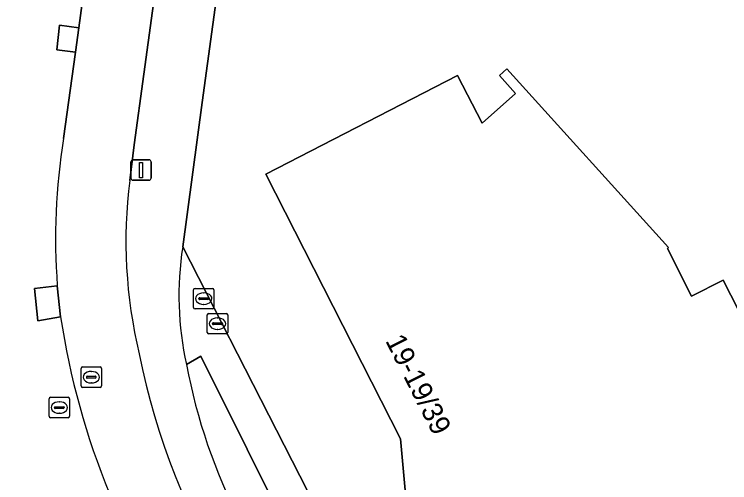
# Model space of a CAD drawing. Extents: x 161402 to 161933, y 381647 to 382315.
# Drawn here: x 161753.62 to 161788.66, y 381978.86 to 382001.78 of the extents above; entities that cross this region are included whole.
import ezdxf

# ---------------------------------------------------------------- set-up
doc = ezdxf.new("R2010")
doc.units = 0
for name, color, linetype in [('IMGEO_Erf', 7, 'Continuous'), ('IMGEO_Groenvoorziening', 7, 'Continuous'), ('IMGEO_Lichtmast', 7, 'Continuous'), ('IMGEO_Pand', 7, 'Continuous'), ('IMGEO_Pand_nummerreeks', 7, 'Continuous'), ('IMGEO_Rijbaan_lokaal_open', 7, 'Continuous'), ('IMGEO_Rioolput', 7, 'Continuous'), ('IMGEO_Voetpad_open', 7, 'Continuous')]:
    doc.layers.add(name, color=color, linetype=linetype)

msp = doc.modelspace()

# ---------------------------------------------------------------- linework, layer by layer
at = {"layer": 'IMGEO_Erf'}
for points in [[(161773.703, 382076.916), (161762.821, 381997.456), (161761.87, 381990.395), (161771.057, 381972.467), (161771.173, 381972.261), (161771.575, 381971.547), (161771.72, 381971.27), (161774.483, 381972.736)], [(161772.785, 381978.319), (161772.541, 381981.009), (161765.944, 381993.952), (161775.334, 381998.777), (161776.531, 381996.448), (161778.17, 381997.911), (161777.382, 381998.782), (161777.752, 381999.117), (161785.669, 381990.368), (161785.621, 381990.324), (161786.795, 381987.989), (161788.334, 381988.775), (161795.171, 381975.426), (161794.738, 381975.207), (161794.625, 381975.432), (161790.711, 381973.405), (161791.79, 381971.32), (161780.758, 381965.653), (161781.596, 381964.647), (161815.795, 381959.903)]]:
    msp.add_lwpolyline(points, dxfattribs=at)
at = {"layer": 'IMGEO_Groenvoorziening'}
for points in [[(161756.039, 381995.697), (161756.622, 381999.921), (161755.702, 382000.039), (161755.845, 382001.24), (161756.786, 382001.123), (161757.438, 382005.955), (161752.007, 382011.44), (161749.264, 381999.612), (161742.845, 382001.573), (161740.844, 381999.927), (161740.748, 381996.108), (161746.467, 381993.537), (161748.45, 381991.402), (161747.827, 381985.564), (161748.917, 381980.449), (161750.906, 381973.96), (161750.941, 381973.847), (161758.283, 381978.333)], [(161755.89, 381986.981), (161754.774, 381986.776), (161754.618, 381988.369), (161755.73, 381988.499)], [(161762.759, 381985.056), (161762.059, 381984.641)], [(161769.391, 381970.434), (161769.954, 381970.692), (161769.557, 381971.429), (161762.759, 381985.056)]]:
    msp.add_lwpolyline(points, dxfattribs=at)
for centre, radius, start, end in [((161786.344, 381990.79), 30.699, 170.8031, 184.2806), ((161792.794, 381992.538), 37.32, 188.5628, 202.372), ((161789.276, 381989.692), 27.681, 190.5129, 224.0822)]:
    msp.add_arc(centre, radius, start, end, dxfattribs=at)
at = {"layer": 'IMGEO_Lichtmast'}
for p, q in [((161759.336, 381993.76), (161759.336, 381994.56)), ((161759.336, 381994.56), (161759.336, 381993.76)), ((161759.436, 381994.66), (161760.226, 381994.66)), ((161760.226, 381994.66), (161759.436, 381994.66)), ((161760.326, 381994.56), (161760.326, 381993.76)), ((161760.326, 381993.76), (161760.326, 381994.56)), ((161760.226, 381993.66), (161759.436, 381993.66)), ((161759.436, 381993.66), (161760.226, 381993.66))]:
    msp.add_line(p, q, dxfattribs=at)
msp.add_lwpolyline([(161759.756, 381994.535), (161759.906, 381994.535), (161759.906, 381993.785), (161759.756, 381993.785), (161759.756, 381994.535)], dxfattribs=at)
for centre, start, end in [((161759.436, 381994.56), 90, 180), ((161759.436, 381994.56), 90, 180), ((161760.226, 381994.56), 0, 90), ((161760.226, 381994.56), 360, 90), ((161759.436, 381993.76), 180, 270), ((161759.436, 381993.76), 180, 270), ((161760.226, 381993.76), 270, 0), ((161760.226, 381993.76), 270, 0)]:
    msp.add_arc(centre, 0.1, start, end, dxfattribs=at)
at = {"layer": 'IMGEO_Pand'}
for points in [[(161788.334, 381988.775), (161786.795, 381987.989), (161785.621, 381990.324), (161785.669, 381990.368), (161777.752, 381999.117), (161777.382, 381998.782), (161778.17, 381997.911), (161776.531, 381996.448), (161775.334, 381998.777), (161765.944, 381993.952), (161772.541, 381981.009), (161772.785, 381978.319)], [(161774.483, 381972.736), (161774.762, 381972.334), (161780.758, 381965.653), (161791.79, 381971.32), (161790.711, 381973.405), (161794.625, 381975.432), (161794.738, 381975.207), (161795.171, 381975.426), (161788.334, 381988.775)]]:
    msp.add_lwpolyline(points, dxfattribs=at)
at = {"layer": 'IMGEO_Rijbaan_lokaal_open'}
for points in [[(161759.283, 381993.653), (161759.49, 381995.39), (161759.969, 381998.846), (161769.695, 382069.904), (161761.399, 382070.432)], [(161765.457, 382064.59), (161764.936, 382060.736), (161764.745, 382059.38), (161762.518, 382042.922), (161762.302, 382041.53), (161759.804, 382023.11), (161758.766, 382015.767), (161757.438, 382005.955), (161756.786, 382001.123), (161756.622, 381999.921), (161756.039, 381995.697)], [(161755.73, 381988.499), (161755.89, 381986.981)]]:
    msp.add_lwpolyline(points, dxfattribs=at)
for centre, radius, start, end in [((161786.344, 381990.79), 30.699, 170.8031, 184.2806), ((161782.545, 381990.658), 23.454, 172.6635, 193.5519), ((161792.794, 381992.538), 37.32, 188.5628, 202.372), ((161793.302, 381991.816), 34.211, 191.2156, 232.7772)]:
    msp.add_arc(centre, radius, start, end, dxfattribs=at)
at = {"layer": 'IMGEO_Rioolput'}
for p, q in [((161762.401, 381987.44), (161762.401, 381988.292)), ((161762.476, 381988.366), (161763.328, 381988.366)), ((161762.889, 381988.146), (161762.914, 381988.146)), ((161763.402, 381988.292), (161763.402, 381987.44)), ((161762.66, 381987.86), (161762.66, 381987.872)), ((161763.098, 381987.823), (161762.7, 381987.823)), ((161762.703, 381987.909), (161763.101, 381987.909)), ((161763.144, 381987.872), (161763.144, 381987.86)), ((161762.912, 381987.586), (161762.887, 381987.586)), ((161763.328, 381987.366), (161762.476, 381987.366)), ((161763.149, 381987.141), (161764.001, 381987.141)), ((161763.074, 381986.215), (161763.074, 381987.067)), ((161763.562, 381986.921), (161763.587, 381986.921)), ((161764.075, 381987.067), (161764.075, 381986.215)), ((161763.333, 381986.635), (161763.333, 381986.647)), ((161763.771, 381986.598), (161763.373, 381986.598)), ((161763.376, 381986.684), (161763.774, 381986.684)), ((161763.817, 381986.647), (161763.817, 381986.635)), ((161764.001, 381986.141), (161763.149, 381986.141)), ((161763.585, 381986.361), (161763.56, 381986.361)), ((161756.895, 381983.597), (161756.895, 381984.449)), ((161756.97, 381984.523), (161757.822, 381984.523)), ((161757.383, 381984.303), (161757.408, 381984.303)), ((161757.896, 381984.449), (161757.896, 381983.597)), ((161757.154, 381984.017), (161757.154, 381984.029)), ((161757.592, 381983.98), (161757.194, 381983.98)), ((161757.197, 381984.066), (161757.595, 381984.066)), ((161757.638, 381984.029), (161757.638, 381984.017)), ((161757.406, 381983.743), (161757.381, 381983.743)), ((161757.822, 381983.523), (161756.97, 381983.523)), ((161755.329, 381982.111), (161755.329, 381982.963)), ((161755.404, 381983.037), (161756.256, 381983.037)), ((161756.33, 381982.963), (161756.33, 381982.111)), ((161755.588, 381982.531), (161755.588, 381982.543)), ((161755.631, 381982.58), (161756.029, 381982.58)), ((161755.817, 381982.817), (161755.842, 381982.817)), ((161756.072, 381982.543), (161756.072, 381982.531)), ((161756.026, 381982.494), (161755.628, 381982.494)), ((161755.84, 381982.257), (161755.815, 381982.257)), ((161756.256, 381982.037), (161755.404, 381982.037))]:
    msp.add_line(p, q, dxfattribs=at)
for points in [[(161762.401, 381987.44), (161762.401, 381988.292)], [(161762.476, 381988.366), (161763.328, 381988.366)], [(161763.402, 381988.292), (161763.402, 381987.44)], [(161763.328, 381987.366), (161762.476, 381987.366)], [(161763.149, 381987.141), (161764.001, 381987.141)], [(161763.074, 381986.215), (161763.074, 381987.067)], [(161764.075, 381987.067), (161764.075, 381986.215)], [(161764.001, 381986.141), (161763.149, 381986.141)], [(161756.895, 381983.597), (161756.895, 381984.449)], [(161756.97, 381984.523), (161757.822, 381984.523)], [(161757.896, 381984.449), (161757.896, 381983.597)], [(161757.822, 381983.523), (161756.97, 381983.523)], [(161755.329, 381982.111), (161755.329, 381982.963)], [(161755.404, 381983.037), (161756.256, 381983.037)], [(161756.33, 381982.963), (161756.33, 381982.111)], [(161756.256, 381982.037), (161755.404, 381982.037)]]:
    msp.add_lwpolyline(points, dxfattribs=at)
for centre, radius, start, end in [((161762.478, 381988.29), 0.0765, 91.552, 178.448), ((161762.478, 381988.29), 0.0765, 91.552, 178.448), ((161763.326, 381988.29), 0.0765, 1.552, 88.448), ((161763.326, 381988.29), 0.0765, 1.552, 88.448), ((161762.7, 381987.869), 0.0403, 85.8775, 175.7526), ((161762.697, 381987.859), 0.0366, 178.938, 274.7102), ((161763.101, 381987.866), 0.043, 264.8664, 352.4533), ((161763.105, 381987.871), 0.0386, 1.7309, 96.639), ((161762.478, 381987.442), 0.0765, 181.552, 268.448), ((161762.478, 381987.442), 0.0765, 181.552, 268.448), ((161763.151, 381987.065), 0.0765, 91.552, 178.448), ((161763.151, 381987.065), 0.0765, 91.552, 178.448), ((161763.326, 381987.442), 0.0765, 271.552, 358.448), ((161763.326, 381987.442), 0.0765, 271.552, 358.448), ((161763.999, 381987.065), 0.0765, 1.552, 88.448), ((161763.999, 381987.065), 0.0765, 1.552, 88.448), ((161763.373, 381986.644), 0.0403, 85.8775, 175.7526), ((161763.37, 381986.634), 0.0366, 178.938, 274.7102), ((161763.774, 381986.641), 0.043, 264.8664, 352.4533), ((161763.778, 381986.646), 0.0386, 1.7309, 96.639), ((161763.151, 381986.217), 0.0765, 181.552, 268.448), ((161763.151, 381986.217), 0.0765, 181.552, 268.448), ((161763.999, 381986.217), 0.0765, 271.552, 358.448), ((161763.999, 381986.217), 0.0765, 271.552, 358.448), ((161756.972, 381984.447), 0.0765, 91.552, 178.448), ((161756.972, 381984.447), 0.0765, 91.552, 178.448), ((161757.82, 381984.447), 0.0765, 1.552, 88.448), ((161757.82, 381984.447), 0.0765, 1.552, 88.448), ((161757.194, 381984.026), 0.0403, 85.8775, 175.7526), ((161757.191, 381984.016), 0.0366, 178.938, 274.7102), ((161757.595, 381984.023), 0.043, 264.8664, 352.4533), ((161757.599, 381984.028), 0.0386, 1.7309, 96.639), ((161756.972, 381983.599), 0.0765, 181.552, 268.448), ((161756.972, 381983.599), 0.0765, 181.552, 268.448), ((161757.82, 381983.599), 0.0765, 271.552, 358.448), ((161757.82, 381983.599), 0.0765, 271.552, 358.448), ((161755.406, 381982.961), 0.0765, 91.552, 178.448), ((161755.406, 381982.961), 0.0765, 91.552, 178.448), ((161756.254, 381982.961), 0.0765, 1.552, 88.448), ((161756.254, 381982.961), 0.0765, 1.552, 88.448), ((161755.628, 381982.54), 0.0403, 85.8775, 175.7526), ((161756.033, 381982.542), 0.0386, 1.7309, 96.639), ((161755.625, 381982.53), 0.0366, 178.938, 274.7102), ((161756.029, 381982.537), 0.043, 264.8664, 352.4533), ((161755.406, 381982.113), 0.0765, 181.552, 268.448), ((161755.406, 381982.113), 0.0765, 181.552, 268.448), ((161756.254, 381982.113), 0.0765, 271.552, 358.448), ((161756.254, 381982.113), 0.0765, 271.552, 358.448)]:
    msp.add_arc(centre, radius, start, end, dxfattribs=at)
for centre, major_axis, ratio, start_param, end_param in [((161762.888, 381987.866), (-0.387, 0.002), 0.722429, 4.712389, 7.853982), ((161762.913, 381987.866), (-0.39, 0.002), 0.717154, 1.570796, 4.712389), ((161763.561, 381986.641), (-0.387, 0.002), 0.722429, 4.712389, 7.853982), ((161763.586, 381986.641), (-0.39, 0.002), 0.717154, 1.570796, 4.712389), ((161757.382, 381984.023), (-0.387, 0.002), 0.722429, 4.712389, 7.853982), ((161757.407, 381984.023), (-0.39, 0.002), 0.717154, 1.570796, 4.712389), ((161755.816, 381982.537), (-0.387, 0.002), 0.722429, 4.712389, 7.853982), ((161755.841, 381982.537), (-0.39, 0.002), 0.717154, 1.570796, 4.712389)]:
    msp.add_ellipse(centre, major_axis=major_axis, ratio=ratio, start_param=start_param, end_param=end_param, dxfattribs=at)
at = {"layer": 'IMGEO_Voetpad_open'}
for points in [[(161761.87, 381990.395), (161762.821, 381997.456), (161773.703, 382076.916), (161776.756, 382099.569), (161777.238, 382100.058), (161781.67, 382104.382), (161804.249, 382126.529), (161826.48, 382148.395), (161845.138, 382166.658), (161857.746, 382179.014)], [(161773.605, 382098.746), (161773.576, 382098.504), (161774.632, 382098.337), (161773.418, 382089.408), (161772.36, 382089.55), (161770.706, 382077.294), (161769.695, 382069.904), (161759.969, 381998.846), (161759.49, 381995.39), (161759.283, 381993.653)], [(161762.059, 381984.641), (161762.759, 381985.056), (161769.557, 381971.429), (161771.173, 381972.261), (161771.057, 381972.467), (161761.87, 381990.395)]]:
    msp.add_lwpolyline(points, dxfattribs=at)
for points in [[(161756.786, 382001.123), (161755.845, 382001.24), (161755.702, 382000.039), (161756.622, 381999.921)], [(161755.73, 381988.499), (161754.618, 381988.369), (161754.774, 381986.776), (161755.89, 381986.981)]]:
    msp.add_lwpolyline(points, close=True, dxfattribs=at)
for centre, radius, start, end in [((161782.545, 381990.658), 23.454, 172.6635, 193.5519), ((161777.164, 381988.017), 15.478, 171.163, 192.5996), ((161777.164, 381988.017), 15.478, 171.163, 192.5996), ((161793.302, 381991.816), 34.211, 191.2156, 232.7772), ((161789.276, 381989.692), 27.681, 190.5129, 224.0822)]:
    msp.add_arc(centre, radius, start, end, dxfattribs=at)

# ---------------------------------------------------------------- texts
at = {"layer": 'IMGEO_Pand_nummerreeks'}
msp.add_text('19-19/39', height=1, rotation=297.009, dxfattribs=at).set_placement((161771.78, 381985.806))

doc.saveas('drawing.dxf')
